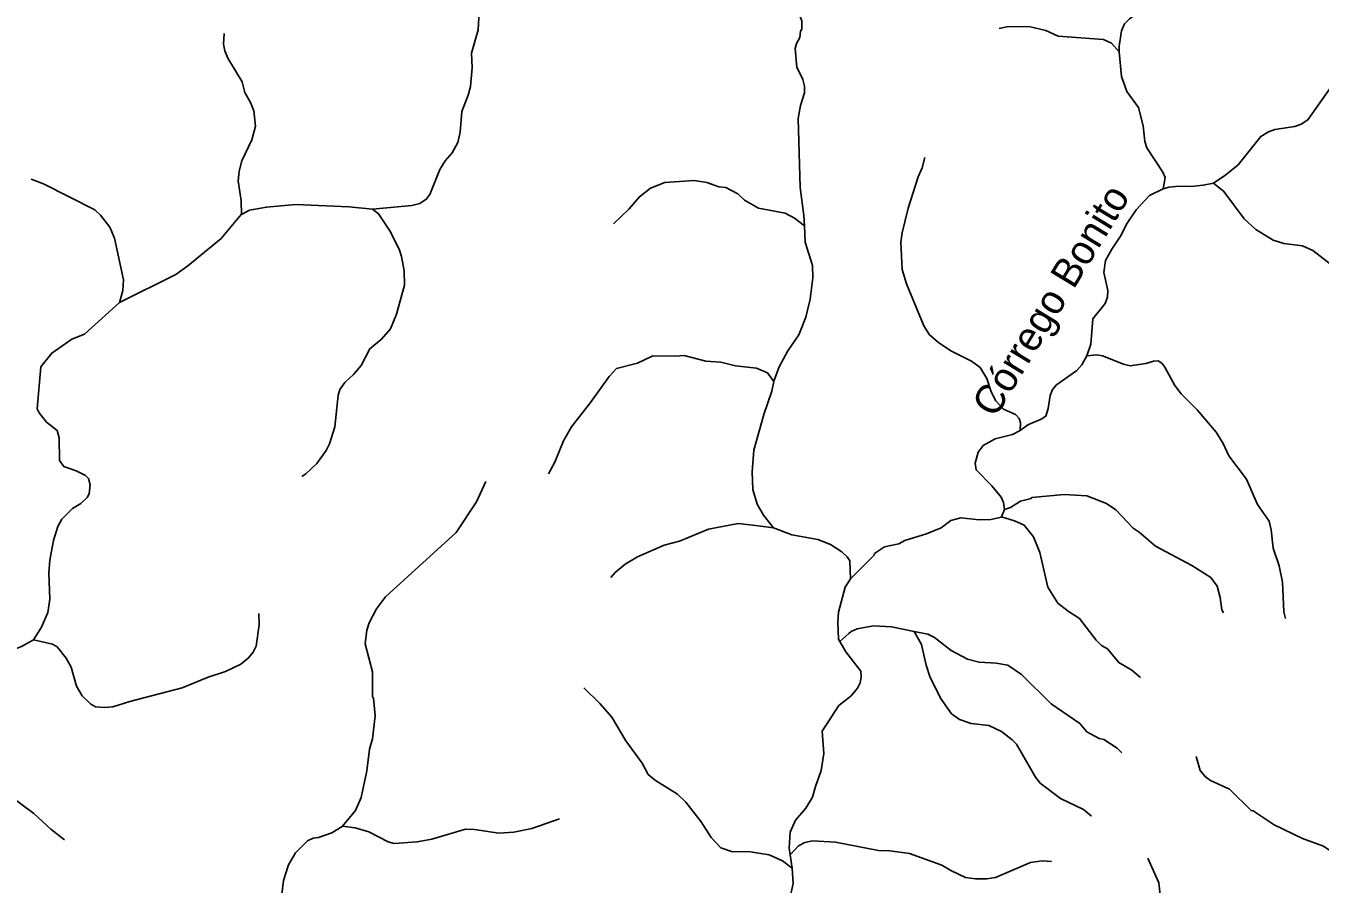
# Model space of a CAD drawing. Extents: x 500 to 555.2, y 9115.7 to 9171.
# Drawn here: x 515.86 to 523.01, y 9147.56 to 9152.3 of the extents above; entities that cross this region are included whole.
import ezdxf
from ezdxf.enums import TextEntityAlignment as Align

# ---------------------------------------------------------------- set-up
doc = ezdxf.new("R2010")
doc.units = 0
doc.header["$LTSCALE"] = 0.064
doc.layers.add('61', color=7, linetype='Continuous')
doc.layers.add('7', color=7, linetype='Continuous', lineweight=25)

msp = doc.modelspace()

# ---------------------------------------------------------------- linework, layer by layer
at = {"layer": '7'}
for p, q in [((521.266, 9149.6294), (521.2489, 9149.5883)), ((520.0816, 9147.7229), (520.0928, 9147.6483))]:
    msp.add_line(p, q, dxfattribs=at)
for points in [[(522.1941, 9152.8615), (522.1897, 9152.8307), (522.1843, 9152.8267), (522.1535, 9152.7231), (522.1415, 9152.613), (522.1175, 9152.5236), (522.0829, 9152.4656), (522.0215, 9152.3879), (521.9562, 9152.3404), (521.9276, 9152.3117), (521.9108, 9152.2729), (521.8993, 9152.1884), (521.899, 9152.157)], [(520.1652, 9152.7014), (520.1442, 9152.6231), (520.1164, 9152.4482), (520.1181, 9152.3967), (520.1456, 9152.3294), (520.1458, 9152.2824), (520.1394, 9152.2718), (520.1358, 9152.2367), (520.1161, 9152.2025), (520.1098, 9152.1752), (520.1189, 9152.073), (520.1508, 9152.004), (520.1605, 9151.9679), (520.1603, 9151.9318), (520.1392, 9151.8603), (520.1262, 9151.7888), (520.1359, 9151.4076), (520.1575, 9151.2532), (520.16, 9151.1965)], [(518.3677, 9152.4475), (518.3575, 9152.2781), (518.3219, 9152.1503), (518.325, 9152.0702), (518.3152, 9151.9659), (518.3037, 9151.9176), (518.2672, 9151.8271), (518.2594, 9151.7132), (518.245, 9151.6565), (518.2151, 9151.5995), (518.1758, 9151.5552), (518.1456, 9151.5079), (518.0914, 9151.3688), (518.0717, 9151.3429), (518.0368, 9151.3193), (517.9916, 9151.3079), (517.7741, 9151.2882)], [(516.9544, 9152.2581), (516.9522, 9152.2002), (516.9582, 9152.1632), (516.9754, 9152.1222), (517.0538, 9151.9915), (517.0688, 9151.9332), (517.1013, 9151.8767), (517.1194, 9151.8323), (517.1275, 9151.7477), (517.108, 9151.6706), (517.0534, 9151.5551), (517.0373, 9151.4981), (517.0325, 9151.4457), (517.0488, 9151.3348), (517.0509, 9151.2593)], [(521.2353, 9152.286), (521.2781, 9152.2949), (521.3993, 9152.2982), (521.494, 9152.2751), (521.5625, 9152.2443), (521.8129, 9152.2259), (521.8566, 9152.2047), (521.899, 9152.157)], [(521.899, 9152.157), (521.9113, 9152.022), (521.9403, 9151.9392), (522.0058, 9151.8492), (522.0319, 9151.7494), (522.0401, 9151.6617), (522.0521, 9151.6268), (522.1399, 9151.4935), (522.1524, 9151.4627), (522.142, 9151.4012)], [(523.1546, 9152.1087), (523.0868, 9151.9883), (522.9418, 9151.7813), (522.9047, 9151.7586), (522.8693, 9151.7457), (522.7589, 9151.7285), (522.7229, 9151.7151), (522.6811, 9151.6899), (522.5569, 9151.5339), (522.4884, 9151.4772), (522.4194, 9151.4317)], [(520.8246, 9151.5731), (520.8102, 9151.5164), (520.7877, 9151.4678), (520.7326, 9151.2948), (520.7001, 9151.1576), (520.6936, 9151.107), (520.7003, 9150.9549), (520.7249, 9150.8757), (520.82, 9150.6433), (520.8513, 9150.5949), (520.9001, 9150.5518), (520.9696, 9150.5051), (521.084, 9150.4496), (521.1311, 9150.4139), (521.1671, 9150.3523), (521.1921, 9150.2797), (521.2172, 9150.23), (521.2592, 9150.1846), (521.3265, 9150.1551), (521.3462, 9150.1328), (521.3529, 9150.1077), (521.3526, 9150.0656)], [(515.8882, 9151.4545), (515.9575, 9151.4284), (516.2402, 9151.2845), (516.2725, 9151.2553), (516.3227, 9151.1894), (516.3501, 9151.1287), (516.3993, 9150.8985), (516.3949, 9150.8393), (516.3773, 9150.7738)], [(519.1054, 9151.2073), (519.1898, 9151.2883), (519.2486, 9151.3566), (519.3103, 9151.4039), (519.39, 9151.4352), (519.551, 9151.447), (519.6208, 9151.4354), (519.6871, 9151.4125), (519.7261, 9151.4074), (519.7923, 9151.373), (519.8291, 9151.3388), (519.9058, 9151.2939), (520.0545, 9151.2661), (520.1052, 9151.2394), (520.16, 9151.1965)], [(522.142, 9151.4012), (522.0665, 9151.3632), (521.9928, 9151.2845), (521.9438, 9151.2113), (521.9057, 9151.1385), (521.8574, 9151.0684), (521.8225, 9151.0046), (521.814, 9150.9384), (521.8354, 9150.8389), (521.8336, 9150.8039), (521.8216, 9150.7674), (521.7539, 9150.6826), (521.7418, 9150.5422), (521.7206, 9150.4777)], [(522.4194, 9151.4317), (522.3634, 9151.4201), (522.2961, 9151.4131), (522.2278, 9151.4162), (522.1741, 9151.4097), (522.142, 9151.4012)], [(523.473, 9150.8034), (523.4489, 9150.8326), (523.4132, 9150.8547), (523.3811, 9150.8596), (523.3148, 9150.8532), (523.2914, 9150.8496), (523.2654, 9150.8612), (523.2393, 9150.8814), (523.1815, 9150.9393), (523.1559, 9150.9562), (523.0661, 9150.9842), (522.9679, 9151.0595), (522.9113, 9151.0859), (522.8084, 9151.0986), (522.7487, 9151.1167), (522.6532, 9151.1768), (522.5894, 9151.2358), (522.4776, 9151.3867), (522.4194, 9151.4317)], [(517.7741, 9151.2882), (517.6433, 9151.3011), (517.3501, 9151.3141), (517.1882, 9151.2995), (517.0942, 9151.2825), (517.0509, 9151.2593)], [(517.0509, 9151.2593), (517.0493, 9151.2585), (516.9384, 9151.1267), (516.7542, 9150.975), (516.6874, 9150.9282), (516.3773, 9150.7738)], [(517.384, 9149.8127), (517.407, 9149.8264), (517.4669, 9149.8839), (517.5177, 9149.9548), (517.5365, 9149.9915), (517.5671, 9150.0855), (517.5851, 9150.2613), (517.5936, 9150.2932), (517.6217, 9150.3316), (517.6698, 9150.3752), (517.7125, 9150.4256), (517.7595, 9150.5174), (517.8244, 9150.5706), (517.8743, 9150.6282), (517.9073, 9150.7076), (517.951, 9150.8686), (517.9494, 9150.9477), (517.9344, 9151.0276), (517.9213, 9151.067), (517.8702, 9151.1692), (517.8082, 9151.2632), (517.7741, 9151.2882)], [(520.16, 9151.1965), (520.1639, 9151.1064), (520.2041, 9150.9772), (520.2063, 9150.9083), (520.1917, 9150.7915), (520.1776, 9150.7309), (520.1685, 9150.6918), (520.1293, 9150.5941), (520.069, 9150.506), (520.0214, 9150.4174), (519.9915, 9150.3391), (519.9912, 9150.3375)], [(516.3773, 9150.7738), (516.1837, 9150.598), (516.1134, 9150.5707), (516.0025, 9150.4938), (515.9427, 9150.4183), (515.9214, 9150.1865), (515.9323, 9150.1637), (515.9746, 9150.1119), (516.0333, 9150.0657), (516.0435, 9150.0249), (516.0449, 9149.8997), (516.0687, 9149.8672), (516.1375, 9149.844), (516.1888, 9149.8168), (516.2055, 9149.8), (516.2155, 9149.7658), (516.2091, 9149.7153), (516.1978, 9149.6957), (516.1631, 9149.6624), (516.1173, 9149.6344), (516.0582, 9149.5754), (516.0355, 9149.535), (516.0121, 9149.4583), (515.9925, 9149.35), (515.986, 9149.2792), (515.9925, 9149.1341), (515.9813, 9149.0603), (515.9469, 9148.9806), (515.9021, 9148.9103)], [(518.7473, 9149.8273), (518.7823, 9149.8914), (518.8296, 9150.0088), (518.8729, 9150.0855), (518.9795, 9150.2201), (519.0809, 9150.3645), (519.1228, 9150.4087), (519.2382, 9150.437), (519.323, 9150.4775), (519.4481, 9150.4759), (519.4956, 9150.4809), (519.6156, 9150.4484), (519.6991, 9150.4431), (519.7789, 9150.4233), (519.8958, 9150.4104), (519.9563, 9150.3846), (519.9912, 9150.3375)], [(521.7206, 9150.4777), (521.6935, 9150.4284), (521.6642, 9150.3968), (521.5527, 9150.3176), (521.5306, 9150.2926), (521.5171, 9150.2593), (521.5072, 9150.1879), (521.4933, 9150.1442), (521.4688, 9150.128), (521.3934, 9150.0974), (521.3526, 9150.0656)], [(522.818, 9149.0279), (522.8079, 9149.0641), (522.801, 9149.2274), (522.7833, 9149.3178), (522.7488, 9149.4168), (522.739, 9149.5179), (522.7272, 9149.5645), (522.6627, 9149.6577), (522.6025, 9149.7974), (522.5045, 9149.9264), (522.4727, 9149.9948), (522.4355, 9150.0576), (522.3294, 9150.1804), (522.2407, 9150.2692), (522.206, 9150.3152), (522.1512, 9150.4155), (522.1336, 9150.4379), (522.1136, 9150.4502), (522.0892, 9150.4494), (522.0455, 9150.4363), (521.9593, 9150.4236), (521.9226, 9150.4325), (521.8067, 9150.4792), (521.7762, 9150.484), (521.7206, 9150.4777)], [(519.9912, 9150.3375), (519.9807, 9150.2826), (519.9356, 9150.1538), (519.8803, 9149.9582), (519.8719, 9149.838), (519.8758, 9149.7401), (519.8986, 9149.6582), (519.9338, 9149.5989), (519.9886, 9149.5283)], [(521.3526, 9150.0656), (521.3091, 9150.0431), (521.2134, 9150.0203), (521.1485, 9149.9825), (521.1199, 9149.947), (521.1038, 9149.8854), (521.1092, 9149.8489), (521.1955, 9149.7607), (521.2478, 9149.6985), (521.2596, 9149.6685), (521.266, 9149.6294)], [(518.3996, 9149.7834), (518.3496, 9149.6721), (518.2368, 9149.502), (517.8468, 9149.1464), (517.7969, 9149.0816), (517.7569, 9149.0034), (517.7427, 9148.963), (517.7346, 9148.8869), (517.7739, 9148.7333), (517.7739, 9148.5957), (517.7794, 9148.5869), (517.7901, 9148.4905), (517.7738, 9148.3633), (517.7577, 9148.3056), (517.7426, 9148.1854), (517.712, 9148.0398), (517.6802, 9147.9679), (517.608, 9147.8798)], [(522.4751, 9149.0593), (522.4663, 9149.076), (522.4569, 9149.144), (522.4404, 9149.2063), (522.406, 9149.2538), (522.3011, 9149.3194), (522.0995, 9149.4264), (522.0102, 9149.5036), (521.9764, 9149.526), (521.8805, 9149.6285), (521.8291, 9149.6629), (521.721, 9149.7047), (521.5941, 9149.7131), (521.4164, 9149.6953), (521.4131, 9149.6904), (521.3547, 9149.6754), (521.2981, 9149.6415), (521.266, 9149.6294)], [(521.2489, 9149.5883), (521.2484, 9149.587), (521.19, 9149.575), (521.1248, 9149.5722), (521.024, 9149.5841), (520.9693, 9149.5687), (520.916, 9149.5275), (520.8355, 9149.4949), (520.7147, 9149.4578), (520.681, 9149.44), (520.6031, 9149.424), (520.5468, 9149.3858), (520.545, 9149.3775), (520.4142, 9149.2474)], [(522.0166, 9148.7018), (521.968, 9148.7416), (521.8966, 9148.784), (521.8344, 9148.8593), (521.802, 9148.8787), (521.7709, 9148.9081), (521.6806, 9149.0279), (521.6175, 9149.0682), (521.5609, 9149.1131), (521.5042, 9149.2012), (521.4598, 9149.3927), (521.4256, 9149.4789), (521.3742, 9149.5422), (521.3208, 9149.5669), (521.2489, 9149.5883)], [(519.0907, 9149.2533), (519.114, 9149.2814), (519.1692, 9149.3268), (519.2386, 9149.3687), (519.3852, 9149.4328), (519.4705, 9149.4543), (519.6295, 9149.5208), (519.7948, 9149.5523), (519.8905, 9149.541), (519.9886, 9149.5283)], [(519.9886, 9149.5283), (520.0901, 9149.4901), (520.235, 9149.4636), (520.3038, 9149.4356), (520.3675, 9149.3958), (520.3966, 9149.3687), (520.4112, 9149.3457), (520.4142, 9149.2474)], [(520.4142, 9149.2474), (520.386, 9149.2011), (520.3492, 9149.0619), (520.3443, 9149.0081), (520.3493, 9148.9137), (520.3564, 9148.9008)], [(517.1469, 9149.0548), (517.1487, 9148.9925), (517.1326, 9148.8756), (517.116, 9148.8422), (517.0902, 9148.8099), (517.0466, 9148.7757), (516.9628, 9148.7355), (516.8672, 9148.7039), (516.723, 9148.6439), (516.4343, 9148.57), (516.3399, 9148.5397), (516.2952, 9148.5355), (516.2437, 9148.5398), (516.2193, 9148.5538), (516.1702, 9148.6006), (516.1397, 9148.6533), (516.11, 9148.7582), (516.0827, 9148.8093), (516.033, 9148.872), (516.0066, 9148.8849), (515.9021, 9148.9103)], [(520.7669, 9148.9567), (520.6405, 9148.9816), (520.5421, 9148.9864), (520.4509, 9148.97), (520.4178, 9148.9561), (520.406, 9148.9454), (520.3564, 9148.9008)], [(521.7469, 9147.9358), (521.7011, 9147.9718), (521.5743, 9148.0331), (521.4629, 9148.1189), (521.4369, 9148.1504), (521.3308, 9148.3327), (521.3081, 9148.3571), (521.2486, 9148.4037), (521.1785, 9148.4371), (521.0808, 9148.4469), (521.0162, 9148.4702), (520.9729, 9148.5006), (520.911, 9148.5881), (520.8528, 9148.7076), (520.8329, 9148.7707), (520.8073, 9148.8844), (520.7669, 9148.9567)], [(521.9142, 9148.2857), (521.8871, 9148.3123), (521.8142, 9148.3588), (521.7883, 9148.365), (521.7198, 9148.4023), (521.6815, 9148.4477), (521.5227, 9148.556), (521.3595, 9148.7191), (521.2837, 9148.7692), (521.2203, 9148.78), (521.1248, 9148.7861), (521.0604, 9148.8036), (520.9714, 9148.8516), (520.8789, 9148.9225), (520.8419, 9148.9419), (520.7669, 9148.9567)], [(515.9021, 9148.9103), (515.8358, 9148.8736), (515.7033, 9148.8221), (515.6698, 9148.8019), (515.554, 9148.709), (515.4935, 9148.6675), (515.3862, 9148.6126), (515.3615, 9148.6022), (515.3304, 9148.5862), (515.297, 9148.5763), (515.0625, 9148.4968), (515.0624, 9148.4967)], [(520.3564, 9148.9008), (520.3884, 9148.843), (520.4716, 9148.7358), (520.4736, 9148.7044), (520.4673, 9148.6723), (520.4534, 9148.6434), (520.4178, 9148.6009), (520.3505, 9148.5463), (520.2578, 9148.405), (520.2671, 9148.2812), (520.2535, 9148.1879), (520.221, 9148.1001), (520.2057, 9148.0404), (520.1674, 9147.98), (520.111, 9147.9131), (520.0818, 9147.8481), (520.0762, 9147.7587), (520.0816, 9147.7229)], [(518.9409, 9148.644), (519.0303, 9148.5583), (519.0972, 9148.4834), (519.1747, 9148.3524), (519.2632, 9148.2287), (519.2973, 9148.1667), (519.3374, 9148.1335), (519.4596, 9148.058), (519.5057, 9148.0125), (519.5898, 9147.9044), (519.6459, 9147.8181), (519.699, 9147.7616), (519.7578, 9147.7412), (519.8617, 9147.7381), (519.9647, 9147.722), (520.0383, 9147.689), (520.0928, 9147.6483)], [(516.0734, 9147.8044), (515.9979, 9147.8641), (515.9044, 9147.951), (515.783, 9148.0406), (515.7423, 9148.0579), (515.6809, 9148.0728), (515.6062, 9148.0697), (515.496, 9148.0765), (515.4444, 9148.0956), (515.281, 9148.1313), (515.2008, 9148.1637), (515.1226, 9148.2115), (515.073, 9148.2756), (515.0297, 9148.3139), (514.9702, 9148.3447), (514.9113, 9148.354)], [(522.3244, 9148.2651), (522.3465, 9148.1873), (522.3755, 9148.1528), (522.4024, 9148.133), (522.5082, 9148.0856), (522.6279, 9147.9665), (522.6388, 9147.9644), (522.7549, 9147.8879), (522.9124, 9147.8123), (523.0282, 9147.7707), (523.1023, 9147.7192), (523.1539, 9147.6496), (523.172, 9147.5954), (523.1756, 9147.5556), (523.1848, 9147.5321)], [(517.608, 9147.8798), (517.6065, 9147.878), (517.5497, 9147.8446), (517.4768, 9147.8174), (517.4459, 9147.8136), (517.4152, 9147.7996), (517.3491, 9147.7338), (517.3107, 9147.6664), (517.2821, 9147.5806), (517.2687, 9147.4617), (517.257, 9147.4201), (517.1621, 9147.3101), (517.1296, 9147.2451), (517.1196, 9147.1452), (517.1293, 9147.0472), (517.126, 9146.8687), (517.1431, 9146.8144)], [(518.8071, 9147.9208), (518.6551, 9147.8668), (518.5547, 9147.8466), (518.4714, 9147.8416), (518.3376, 9147.8629), (518.2884, 9147.8645), (518.1025, 9147.8089), (518.0212, 9147.7938), (517.8936, 9147.7847), (517.8619, 9147.7944), (517.7551, 9147.8489), (517.6787, 9147.8711), (517.608, 9147.8798)], [(521.5249, 9147.6854), (521.4744, 9147.6889), (521.4089, 9147.6792), (521.2157, 9147.5973), (521.1673, 9147.589), (521.1056, 9147.589), (521.0501, 9147.5977), (520.9693, 9147.635), (520.9194, 9147.6646), (520.7401, 9147.7298), (520.6313, 9147.7448), (520.5689, 9147.7469), (520.3322, 9147.7924), (520.2057, 9147.799), (520.1631, 9147.7909), (520.1277, 9147.7726), (520.0816, 9147.7229)], [(522.057, 9147.703), (522.1183, 9147.568), (522.1255, 9147.501), (522.1255, 9147.4354), (522.1157, 9147.3791), (522.0616, 9147.192), (522.0672, 9147.0964), (522.0907, 9147.0371), (522.124, 9147.0018), (522.2093, 9146.9488), (522.2736, 9146.805), (522.3449, 9146.7313), (522.3848, 9146.6754), (522.4262, 9146.6339), (522.5576, 9146.5318), (522.6008, 9146.5147), (522.6675, 9146.4711), (522.7232, 9146.4106), (522.7653, 9146.3769), (522.8577, 9146.3299), (522.9039, 9146.2536)], [(520.0928, 9147.6483), (520.0979, 9147.5641), (520.0638, 9147.4053), (520.0571, 9147.3068), (520.0274, 9147.1808), (520.0041, 9147.0331), (519.9879, 9146.9936), (519.9417, 9146.954), (519.8857, 9146.9325), (519.8325, 9146.9), (519.7921, 9146.845), (519.7883, 9146.822), (519.7925, 9146.7861), (519.8043, 9146.7597), (519.8238, 9146.735), (519.8626, 9146.7095), (519.8965, 9146.6968), (519.9214, 9146.6947), (519.9614, 9146.674), (519.9881, 9146.6507), (520.0304, 9146.5571), (520.0561, 9146.4837)]]:
    msp.add_lwpolyline(points, dxfattribs=at)

# ---------------------------------------------------------------- texts
at = {"layer": '61'}
msp.add_text('Córrego Bonito', height=0.16, rotation=58.671, dxfattribs=at).set_placement((521.5885, 9150.7444), align=Align.CENTER)

doc.saveas('drawing.dxf')
